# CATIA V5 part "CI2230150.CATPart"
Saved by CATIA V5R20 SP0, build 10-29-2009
Part number: CI2230150
Bounding box of the stored display mesh (mm): x -29 to 29, y -23.836 to 195, z -41.554 to 32.071
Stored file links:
  C:\Users\Raffaele\Desktop\3D X SITO CF\BOLEX\19-INCLINED ASSEMBLY REF_CI\CI2230150.CATPart
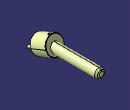
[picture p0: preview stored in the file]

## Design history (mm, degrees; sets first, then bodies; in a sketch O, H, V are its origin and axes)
Set1
  DatumSurface1 to DatumSurface16 "MANIFOLD_SOLID_BREP #395"
  DatumSurface17 to DatumSurface39 "MANIFOLD_SOLID_BREP #1169"
Body1 (main body)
